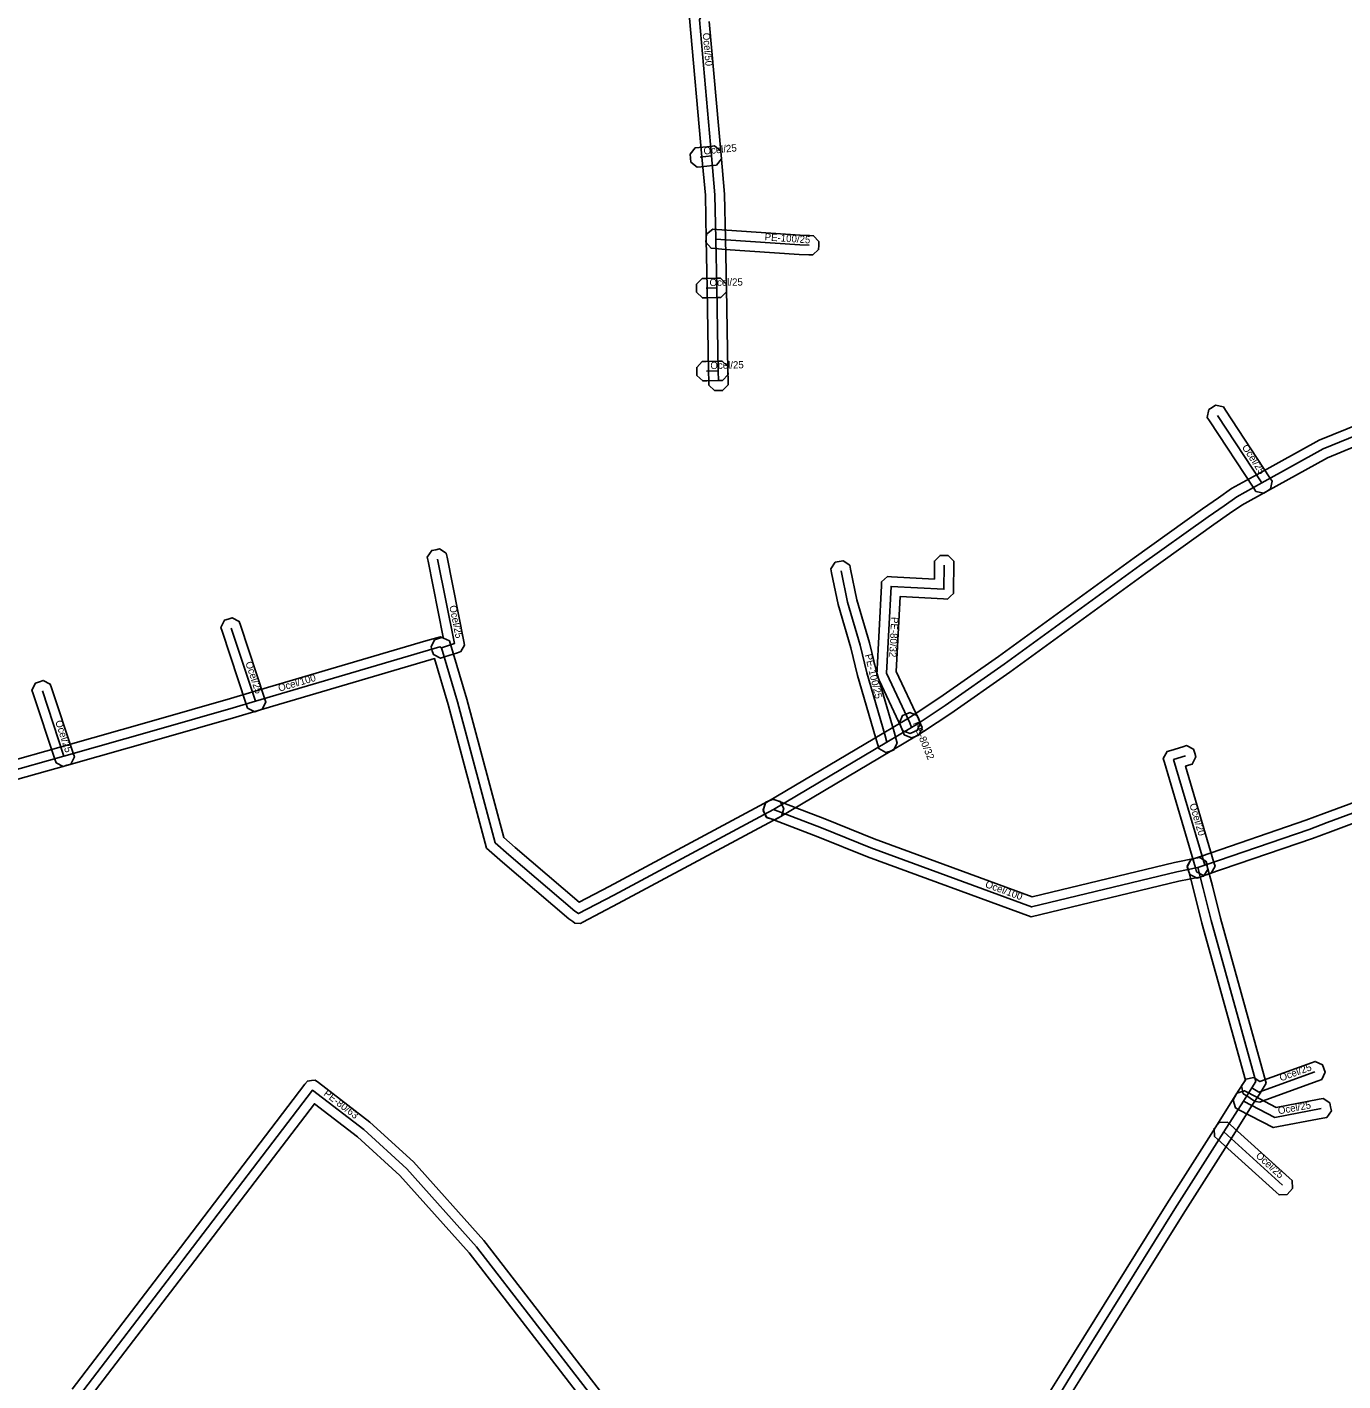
# Model space of a CAD drawing. Extents: x -569373 to -565022, y -1135090 to -1131496.
# Drawn here: x -565687.7 to -565551.4, y -1133846.6 to -1133706.4 of the extents above; entities that cross this region are included whole.
import ezdxf

# ---------------------------------------------------------------- set-up
doc = ezdxf.new("R2010")
doc.units = 0
for name, color, linetype in [('1', 7, 'Continuous'), ('24', 7, 'Continuous'), ('30', 7, 'Continuous')]:
    doc.layers.add(name, color=color, linetype=linetype)

msp = doc.modelspace()

# ---------------------------------------------------------------- linework, layer by layer
at = {"layer": '1'}
for points in [[(-565617.041, -1133705.832), (-565615.804, -1133719.671), (-565615.441, -1133723.726), (-565615.35, -1133728.341), (-565615.26, -1133733.412), (-565615.1, -1133742.001), (-565615.08, -1133743.041), (-565615.072, -1133743.455), (-565615.647, -1133744.052), (-565616.061, -1133744.06), (-565616.475, -1133744.068), (-565617.072, -1133743.493), (-565617.08, -1133743.079), (-565617.1, -1133742.039), (-565617.26, -1133733.448), (-565617.35, -1133728.379), (-565617.439, -1133723.834), (-565617.796, -1133719.849), (-565619.079, -1133705.488)], [(-565548.721, -1133749.275), (-565552.967, -1133751.013), (-565559.287, -1133754.505), (-565561.851, -1133755.92), (-565563.119, -1133756.806), (-565564.754, -1133757.947), (-565571.836, -1133762.991), (-565585.89, -1133773.224), (-565592.016, -1133777.496), (-565594.844, -1133779.384), (-565595.547, -1133779.808), (-565598.11, -1133781.33), (-565609.87, -1133788.31), (-565610.226, -1133788.521), (-565611.029, -1133788.316), (-565611.24, -1133787.96), (-565611.451, -1133787.604), (-565611.246, -1133786.801), (-565610.89, -1133786.59), (-565599.13, -1133779.61), (-565596.573, -1133778.092), (-565595.916, -1133777.696), (-565593.144, -1133775.844), (-565587.05, -1133771.596), (-565573.004, -1133761.369), (-565565.906, -1133756.313), (-565564.265, -1133755.166), (-565562.909, -1133754.22), (-565560.253, -1133752.755), (-565553.833, -1133749.207), (-565549.479, -1133747.425)], [(-565690.325, -1133782.689), (-565684.182, -1133780.958), (-565674.604, -1133778.248), (-565666.659, -1133775.96), (-565664.342, -1133775.281), (-565646.398, -1133769.989), (-565644.873, -1133769.556), (-565643.96, -1133769.985), (-565642.158, -1133776.018), (-565638.331, -1133790.353), (-565637.163, -1133791.396), (-565630.501, -1133797.058), (-565627.408, -1133795.436), (-565610.852, -1133786.568), (-565610.487, -1133786.372), (-565609.694, -1133786.613), (-565609.498, -1133786.978), (-565609.302, -1133787.343), (-565609.543, -1133788.136), (-565609.908, -1133788.332), (-565626.472, -1133797.204), (-565630.135, -1133799.126), (-565630.387, -1133799.258), (-565630.955, -1133799.217), (-565631.185, -1133799.051), (-565631.577, -1133798.768), (-565638.477, -1133792.904), (-565640.109, -1133791.447), (-565644.082, -1133776.562), (-565645.501, -1133771.814), (-565645.842, -1133771.911), (-565663.778, -1133777.199), (-565666.101, -1133777.88), (-565674.056, -1133780.172), (-565683.638, -1133782.882), (-565689.775, -1133784.611)], [(-565546.464, -1133787.468), (-565552.645, -1133789.754), (-565554.534, -1133790.452), (-565565.366, -1133794.166), (-565566.096, -1133794.416), (-565566.488, -1133794.55), (-565567.232, -1133794.186), (-565567.366, -1133793.794), (-565567.5, -1133793.402), (-565567.136, -1133792.658), (-565566.744, -1133792.524), (-565566.014, -1133792.274), (-565555.206, -1133788.568), (-565553.339, -1133787.878), (-565547.156, -1133785.592)], [(-565581.702, -1133847.696), (-565580.34, -1133845.483), (-565569.626, -1133828.297), (-565564.544, -1133820.314), (-565562.524, -1133817.124), (-565561.643, -1133815.741), (-565561.473, -1133815.477), (-565565.988, -1133799.213), (-565566.808, -1133795.869), (-565567.385, -1133793.73), (-565567.493, -1133793.33), (-565567.08, -1133792.613), (-565566.68, -1133792.505), (-565566.28, -1133792.397), (-565565.563, -1133792.81), (-565565.455, -1133793.21), (-565564.872, -1133795.371), (-565564.052, -1133798.707), (-565559.307, -1133815.803), (-565559.957, -1133816.819), (-565560.836, -1133818.196), (-565562.856, -1133821.386), (-565567.934, -1133829.363), (-565578.64, -1133846.537), (-565579.998, -1133848.744)], [(-565683.056, -1133847.495), (-565673.112, -1133834.485), (-565672.385, -1133833.533), (-565658.935, -1133815.913), (-565658.683, -1133815.583), (-565658.271, -1133815.529), (-565657.859, -1133815.474), (-565657.53, -1133815.728), (-565652.197, -1133819.833), (-565647.669, -1133823.965), (-565640.381, -1133832.1), (-565628.421, -1133847.596)], [(-565629.999, -1133848.824), (-565641.919, -1133833.38), (-565649.091, -1133825.375), (-565653.483, -1133821.367), (-565657.954, -1133817.925), (-565670.795, -1133834.747), (-565671.524, -1133835.699), (-565681.524, -1133848.785)]]:
    msp.add_lwpolyline(points, dxfattribs=at)
for points in [[(-565616.288, -1133720.714), (-565616.7, -1133720.755), (-565617.89, -1133720.875), (-565618.302, -1133720.916), (-565618.944, -1133720.392), (-565618.985, -1133719.98), (-565619.026, -1133719.568), (-565618.502, -1133718.926), (-565618.09, -1133718.885), (-565616.9, -1133718.765), (-565616.488, -1133718.724), (-565615.846, -1133719.248), (-565615.805, -1133719.66), (-565615.764, -1133720.072)], [(-565606.307, -1133730.016), (-565606.721, -1133729.999), (-565607.714, -1133729.959), (-565615.376, -1133729.447), (-565616.435, -1133729.356), (-565616.848, -1133729.321), (-565617.382, -1133728.688), (-565617.346, -1133728.275), (-565617.311, -1133727.862), (-565616.678, -1133727.328), (-565616.265, -1133727.364), (-565615.224, -1133727.453), (-565607.606, -1133727.961), (-565606.639, -1133728.001), (-565606.225, -1133728.018), (-565605.664, -1133728.627), (-565605.681, -1133729.041), (-565605.698, -1133729.455)], [(-565615.828, -1133734.422), (-565616.242, -1133734.43), (-565617.332, -1133734.45), (-565617.746, -1133734.457), (-565618.342, -1133733.882), (-565618.35, -1133733.468), (-565618.357, -1133733.054), (-565617.782, -1133732.458), (-565617.368, -1133732.45), (-565616.278, -1133732.43), (-565615.864, -1133732.423), (-565615.268, -1133732.998), (-565615.26, -1133733.412), (-565615.253, -1133733.826)], [(-565615.661, -1133743.01), (-565616.075, -1133743.02), (-565617.295, -1133743.05), (-565617.709, -1133743.06), (-565618.31, -1133742.489), (-565618.32, -1133742.075), (-565618.33, -1133741.661), (-565617.759, -1133741.06), (-565617.345, -1133741.05), (-565616.125, -1133741.02), (-565615.711, -1133741.01), (-565615.11, -1133741.581), (-565615.1, -1133741.995), (-565615.09, -1133742.409)], [(-565560.379, -1133754.525), (-565560.606, -1133754.179), (-565565.196, -1133747.189), (-565565.423, -1133746.843), (-565565.255, -1133746.031), (-565564.909, -1133745.804), (-565564.563, -1133745.577), (-565563.751, -1133745.745), (-565563.524, -1133746.091), (-565558.934, -1133753.081), (-565558.707, -1133753.427), (-565558.875, -1133754.239), (-565559.221, -1133754.466), (-565559.567, -1133754.693)], [(-565645.494, -1133769.877), (-565645.1, -1133769.749), (-565644.595, -1133769.585), (-565646.171, -1133761.716), (-565646.252, -1133761.31), (-565645.792, -1133760.621), (-565645.386, -1133760.539), (-565644.98, -1133760.458), (-565644.291, -1133760.918), (-565644.209, -1133761.324), (-565642.459, -1133770.064), (-565642.385, -1133770.437), (-565642.769, -1133771.093), (-565643.13, -1133771.211), (-565644.48, -1133771.651), (-565644.874, -1133771.779), (-565645.613, -1133771.404), (-565645.741, -1133771.01), (-565645.869, -1133770.616)], [(-565602.471, -1133762.138), (-565602.389, -1133762.544), (-565601.748, -1133765.75), (-565600.444, -1133770.181), (-565599.754, -1133773.042), (-565597.89, -1133779.391), (-565597.659, -1133780.194), (-565597.545, -1133780.592), (-565597.946, -1133781.317), (-565598.344, -1133781.431), (-565598.742, -1133781.545), (-565599.467, -1133781.144), (-565599.581, -1133780.746), (-565599.81, -1133779.949), (-565601.686, -1133773.558), (-565602.376, -1133770.699), (-565603.692, -1133766.23), (-565604.351, -1133762.936), (-565604.432, -1133762.53), (-565603.972, -1133761.841), (-565603.566, -1133761.759), (-565603.16, -1133761.678)], [(-565591.698, -1133761.73), (-565591.7, -1133762.144), (-565591.71, -1133764.644), (-565591.712, -1133765.073), (-565592.023, -1133765.367), (-565592.335, -1133765.661), (-565592.763, -1133765.639), (-565597.254, -1133765.401), (-565597.658, -1133773.142), (-565595.345, -1133778.065), (-565595.169, -1133778.44), (-565595.45, -1133779.219), (-565595.825, -1133779.395), (-565596.2, -1133779.571), (-565596.979, -1133779.29), (-565597.155, -1133778.915), (-565599.682, -1133773.538), (-565599.199, -1133764.298), (-565599.177, -1133763.884), (-565598.869, -1133763.607), (-565598.561, -1133763.33), (-565598.147, -1133763.351), (-565593.706, -1133763.586), (-565593.7, -1133762.136), (-565593.698, -1133761.722), (-565593.11, -1133761.138), (-565592.696, -1133761.14), (-565592.282, -1133761.142)], [(-565664.879, -1133776.948), (-565665.009, -1133776.555), (-565667.519, -1133768.985), (-565667.649, -1133768.592), (-565667.278, -1133767.851), (-565666.885, -1133767.721), (-565666.492, -1133767.591), (-565665.751, -1133767.962), (-565665.621, -1133768.355), (-565663.111, -1133775.925), (-565662.981, -1133776.318), (-565663.352, -1133777.059), (-565663.745, -1133777.189), (-565664.138, -1133777.319)], [(-565684.73, -1133782.627), (-565684.86, -1133782.234), (-565687.09, -1133775.484), (-565687.22, -1133775.09), (-565686.847, -1133774.35), (-565686.454, -1133774.22), (-565686.06, -1133774.09), (-565685.32, -1133774.463), (-565685.19, -1133774.856), (-565682.96, -1133781.606), (-565682.83, -1133782), (-565683.203, -1133782.74), (-565683.596, -1133782.87), (-565683.99, -1133783)], [(-565595.484, -1133777.725), (-565595.326, -1133778.108), (-565595.136, -1133778.568), (-565594.978, -1133778.951), (-565595.295, -1133779.716), (-565595.678, -1133779.874), (-565596.061, -1133780.032), (-565596.826, -1133779.715), (-565596.984, -1133779.332), (-565597.174, -1133778.872), (-565597.332, -1133778.489), (-565597.015, -1133777.724), (-565596.632, -1133777.566), (-565596.249, -1133777.408)], [(-565566.532, -1133793.9), (-565566.649, -1133793.503), (-565569.869, -1133782.573), (-565569.985, -1133782.179), (-565569.597, -1133781.456), (-565569.205, -1133781.335), (-565567.975, -1133780.955), (-565567.579, -1133780.832), (-565566.847, -1133781.219), (-565566.725, -1133781.615), (-565566.602, -1133782.011), (-565566.989, -1133782.743), (-565567.385, -1133782.865), (-565567.672, -1133782.954), (-565564.731, -1133792.937), (-565564.614, -1133793.335), (-565565.01, -1133794.062), (-565565.407, -1133794.179), (-565565.805, -1133794.296)], [(-565610.408, -1133786.368), (-565610.021, -1133786.517), (-565605.044, -1133788.429), (-565599.931, -1133790.487), (-565583.57, -1133796.497), (-565568.807, -1133792.934), (-565566.619, -1133792.49), (-565566.213, -1133792.408), (-565565.522, -1133792.865), (-565565.44, -1133793.271), (-565565.358, -1133793.677), (-565565.815, -1133794.368), (-565566.221, -1133794.45), (-565568.373, -1133794.886), (-565583.69, -1133798.583), (-565600.649, -1133792.353), (-565605.776, -1133790.291), (-565610.739, -1133788.383), (-565611.125, -1133788.235), (-565611.462, -1133787.478), (-565611.313, -1133787.091), (-565611.165, -1133786.705)], [(-565560.604, -1133815.216), (-565560.256, -1133815.441), (-565559.965, -1133815.63), (-565554.633, -1133813.681), (-565554.244, -1133813.539), (-565553.493, -1133813.888), (-565553.351, -1133814.277), (-565553.209, -1133814.666), (-565553.558, -1133815.417), (-565553.947, -1133815.559), (-565559.747, -1133817.679), (-565559.968, -1133817.76), (-565560.436, -1133817.707), (-565560.634, -1133817.579), (-565561.344, -1133817.119), (-565561.692, -1133816.894), (-565561.864, -1133816.084), (-565561.639, -1133815.736), (-565561.414, -1133815.388)], [(-565553.037, -1133819.346), (-565553.444, -1133819.423), (-565558.595, -1133820.397), (-565562.142, -1133818.547), (-565562.509, -1133818.355), (-565562.758, -1133817.565), (-565562.567, -1133817.198), (-565562.375, -1133816.831), (-565561.585, -1133816.582), (-565561.218, -1133816.773), (-565558.285, -1133818.303), (-565553.816, -1133817.457), (-565553.409, -1133817.38), (-565552.724, -1133817.847), (-565552.647, -1133818.254), (-565552.57, -1133818.661)], [(-565563.335, -1133819.831), (-565563.028, -1133820.109), (-565556.948, -1133825.619), (-565556.641, -1133825.897), (-565556.601, -1133826.725), (-565556.879, -1133827.032), (-565557.157, -1133827.339), (-565557.985, -1133827.379), (-565558.292, -1133827.101), (-565564.372, -1133821.591), (-565564.679, -1133821.313), (-565564.719, -1133820.485), (-565564.441, -1133820.178), (-565564.163, -1133819.871)]]:
    msp.add_lwpolyline(points, close=True, dxfattribs=at)
at = {"layer": '24'}
for points in [[(-565616.08, -1133743.06), (-565616.1, -1133742.02), (-565616.26, -1133733.43), (-565616.35, -1133728.36), (-565616.44, -1133723.78), (-565616.8, -1133719.76), (-565618.06, -1133705.66), (-565617.52, -1133704.46), (-565617.61, -1133696.94), (-565619.98, -1133671.67)], [(-565616.8, -1133719.76), (-565617.99, -1133719.88)], [(-565606.68, -1133729), (-565607.66, -1133728.96), (-565615.3, -1133728.45), (-565616.35, -1133728.36)], [(-565616.26, -1133733.43), (-565617.35, -1133733.45)], [(-565616.1, -1133742.02), (-565617.32, -1133742.05)], [(-565559.77, -1133753.63), (-565564.36, -1133746.64)], [(-565610.38, -1133787.45), (-565598.62, -1133780.47), (-565596.06, -1133778.95), (-565595.38, -1133778.54), (-565592.58, -1133776.67), (-565586.47, -1133772.41), (-565572.42, -1133762.18), (-565565.33, -1133757.13), (-565563.692, -1133755.986), (-565562.38, -1133755.07), (-565559.77, -1133753.63), (-565553.4, -1133750.11), (-565549.1, -1133748.35)], [(-565644.79, -1133770.7), (-565643.44, -1133770.26), (-565645.19, -1133761.52)], [(-565603.37, -1133762.74), (-565602.72, -1133765.99), (-565601.41, -1133770.44), (-565600.72, -1133773.3), (-565598.85, -1133779.67), (-565598.62, -1133780.47)], [(-565592.7, -1133762.14), (-565592.71, -1133764.64), (-565598.2, -1133764.35), (-565598.67, -1133773.34), (-565596.25, -1133778.49)], [(-565664.06, -1133776.24), (-565666.57, -1133768.67)], [(-565731.79, -1133781.17), (-565731.31, -1133781.25), (-565731.31, -1133781.8), (-565722.45, -1133782.79), (-565719.69, -1133783.09), (-565696.98, -1133785.66), (-565690.05, -1133783.65), (-565683.91, -1133781.92), (-565674.33, -1133779.21), (-565666.38, -1133776.92), (-565664.06, -1133776.24), (-565646.12, -1133770.95), (-565644.96, -1133770.62), (-565644.79, -1133770.7), (-565643.12, -1133776.29), (-565639.22, -1133790.9), (-565637.82, -1133792.15), (-565630.96, -1133797.98), (-565630.6, -1133798.24), (-565626.94, -1133796.32), (-565610.38, -1133787.45)], [(-565683.91, -1133781.92), (-565686.14, -1133775.17)], [(-565596.25, -1133778.49), (-565596.06, -1133778.95)], [(-565565.69, -1133793.22), (-565568.91, -1133782.29), (-565567.68, -1133781.91)], [(-565546.81, -1133786.53), (-565552.992, -1133788.816), (-565554.87, -1133789.51), (-565565.69, -1133793.22), (-565566.42, -1133793.47)], [(-565610.38, -1133787.45), (-565605.41, -1133789.36), (-565600.29, -1133791.42), (-565583.63, -1133797.54), (-565568.59, -1133793.91), (-565566.42, -1133793.47)], [(-565566.42, -1133793.47), (-565565.84, -1133795.62), (-565565.02, -1133798.96), (-565560.39, -1133815.64), (-565560.8, -1133816.28), (-565561.68, -1133817.66), (-565563.7, -1133820.85), (-565568.78, -1133828.83), (-565579.49, -1133846.01), (-565580.85, -1133848.22)], [(-565560.8, -1133816.28), (-565560.09, -1133816.74), (-565554.29, -1133814.62)], [(-565689.7, -1133854.98), (-565688.56, -1133853.76), (-565685.35, -1133851.44), (-565682.29, -1133848.14), (-565672.318, -1133835.092), (-565671.59, -1133834.14), (-565658.14, -1133816.52), (-565652.84, -1133820.6), (-565648.38, -1133824.67), (-565641.15, -1133832.74), (-565629.21, -1133848.21), (-565623.69, -1133855.25)], [(-565553.63, -1133818.44), (-565558.44, -1133819.35), (-565561.68, -1133817.66)], [(-565563.7, -1133820.85), (-565557.62, -1133826.36)]]:
    msp.add_lwpolyline(points, dxfattribs=at)

# ---------------------------------------------------------------- texts
at = {"layer": '30'}
for s, rotation, p in [('Ocel/50', 275.10648, (-565617.719, -1133707.033)), ('Ocel/25', 5.75826, (-565617.595, -1133719.62)), ('PE-100/25', 356.18095, (-565611.316, -1133728.503)), ('Ocel/25', 1.05118, (-565617.005, -1133733.24)), ('Ocel/25', 1.40863, (-565616.91, -1133741.835)), ('Ocel/25', 303.291, (-565561.865, -1133749.935)), ('Ocel/25', 281.32254, (-565643.976, -1133766.386)), ('PE-80/32', 267.00728, (-565598.175, -1133767.493)), ('PE-100/25', 283.56391, (-565600.922, -1133771.436)), ('Ocel/25', 288.34408, (-565665.115, -1133772.255)), ('Ocel/100', 16.4293, (-565661.588, -1133775.252)), ('Ocel/25', 288.28202, (-565684.825, -1133778.345)), ('PE-80/32', 292.44275, (-565595.955, -1133778.52)), ('Ocel/20', 286.41508, (-565567.282, -1133786.938)), ('Ocel/100', 339.82935, (-565588.502, -1133795.477)), ('Ocel/25', 20.07823, (-565557.787, -1133815.625)), ('PE-80/63', 322.41052, (-565657.056, -1133817)), ('Ocel/25', 10.71312, (-565558.03, -1133819.035)), ('Ocel/25', 317.81556, (-565560.46, -1133823.405))]:
    msp.add_text(s, height=0.75, rotation=rotation, dxfattribs=at).set_placement(p)

doc.saveas('drawing.dxf')
